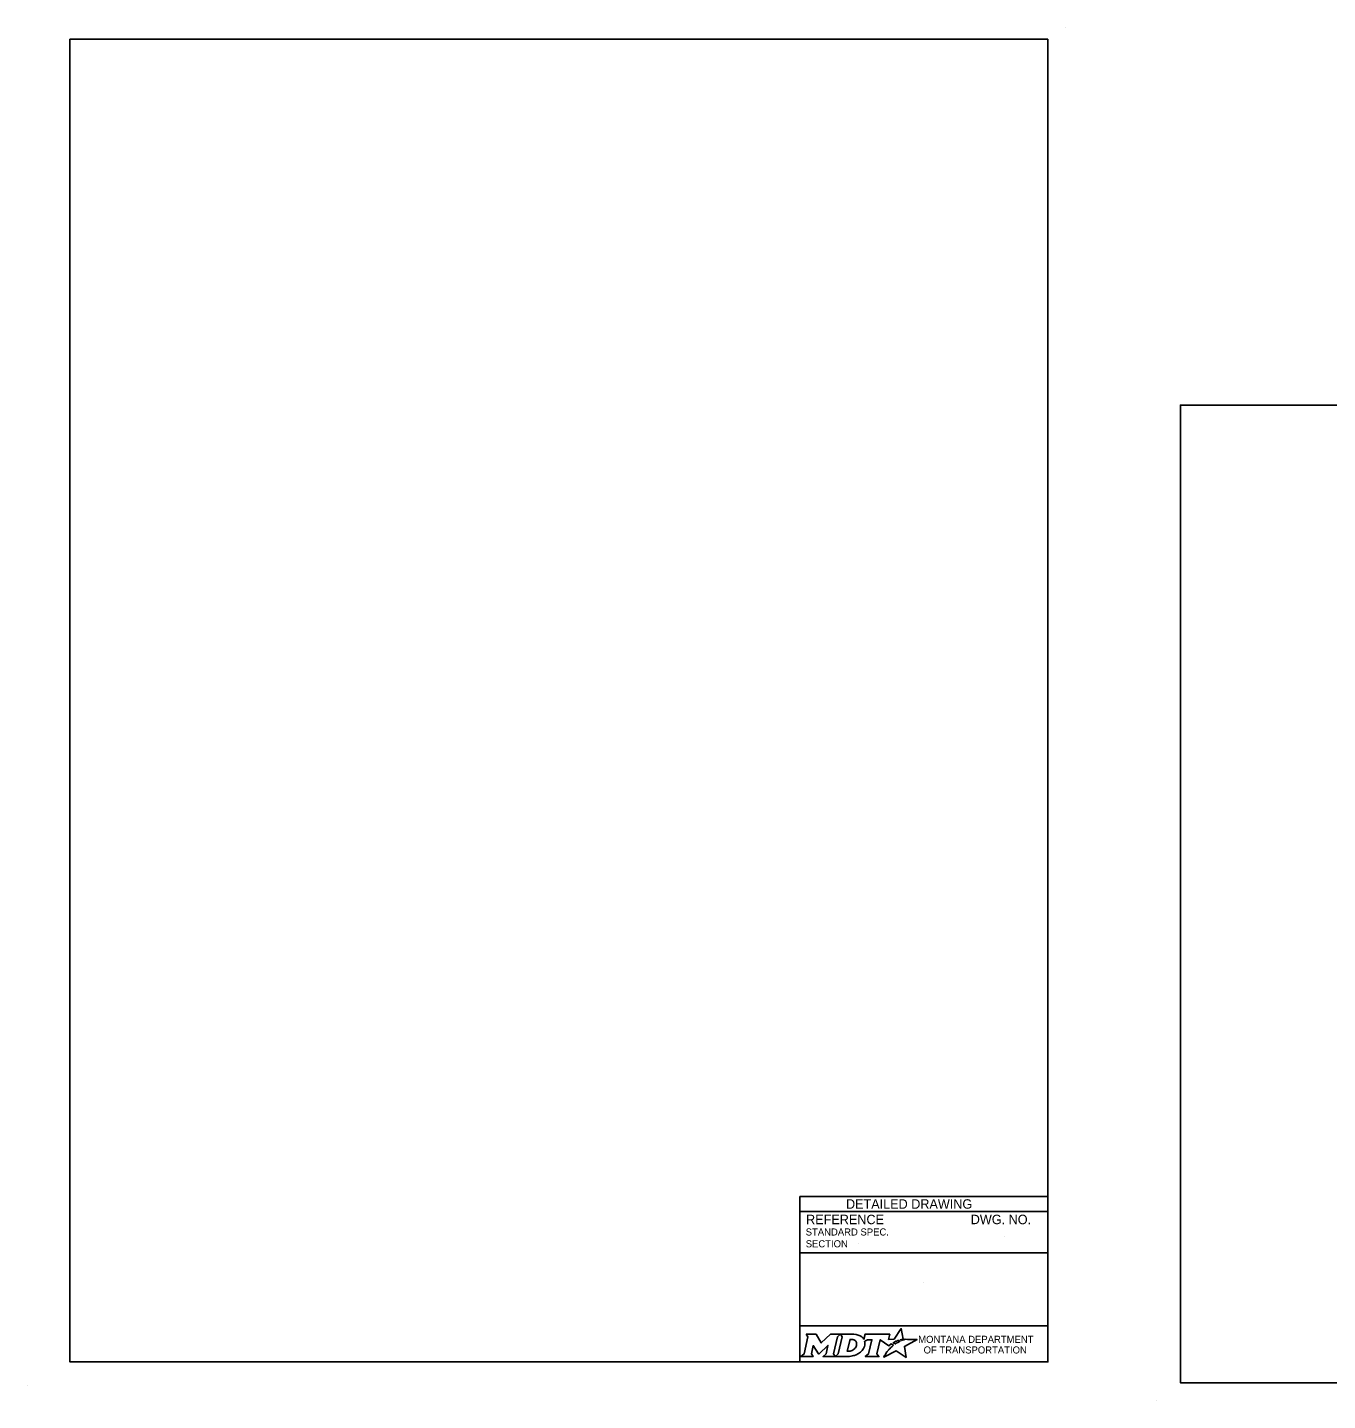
# Model space of a CAD drawing. Extents: x 49991.4 to 50021, y 49987.6 to 50011.4.
# Drawn here: x 49999.98 to 50010.98, y 49999.74 to 50011.36 of the extents above; entities that cross this region are included whole.
import ezdxf

# ---------------------------------------------------------------- set-up
doc = ezdxf.new("R2010")
doc.units = 0
doc.layers.add('Level 1', color=7, linetype='Continuous')
doc.layers.add('Level 2', color=7, linetype='Continuous')

msp = doc.modelspace()

# ---------------------------------------------------------------- linework, layer by layer
at = {"layer": 'Level 1'}
for p, q in [((50008.765, 50011.363), (50008.765, 50011.363)), ((49999.977, 49999.862), (49999.977, 49999.862)), ((50009.537, 49999.736), (50009.537, 49999.736))]:
    msp.add_line(p, q, dxfattribs=at)
for points in [[(50008.615, 50011.263), (50000.336, 50011.263), (50000.336, 50000.062), (50008.615, 50000.062)], [(50020.938, 50008.165), (50009.737, 50008.165), (50009.737, 49999.886), (50020.938, 49999.886)]]:
    msp.add_lwpolyline(points, close=True, dxfattribs=at)
at = {"layer": 'Level 2'}
for p, q in [((50008.615, 50001.462), (50006.515, 50001.462)), ((50006.515, 50001.462), (50006.515, 50000.062)), ((50008.615, 50001.337), (50006.515, 50001.337)), ((50007.009, 50001.063), (50007.009, 50001.063)), ((50008.251, 50001.122), (50008.251, 50001.122)), ((50008.615, 50000.987), (50006.515, 50000.987)), ((50007.565, 50000.738), (50007.565, 50000.738)), ((50008.615, 50000.369), (50006.515, 50000.369))]:
    msp.add_line(p, q, dxfattribs=at)
for points in [[(50007.377, 50000.245), (50007.367, 50000.25), (50007.378, 50000.253), (50007.39, 50000.255), (50007.373, 50000.345), (50007.313, 50000.254), (50007.266, 50000.253), (50007.276, 50000.297), (50007.067, 50000.297), (50007.057, 50000.255), (50007.051, 50000.263)], [(50006.57, 50000.297), (50006.584, 50000.274), (50006.551, 50000.131), (50006.525, 50000.108), (50006.627, 50000.108), (50006.613, 50000.131), (50006.629, 50000.201), (50006.673, 50000.132), (50006.678, 50000.132), (50006.753, 50000.202), (50006.737, 50000.13), (50006.712, 50000.108), (50006.814, 50000.108), (50006.8, 50000.132), (50006.833, 50000.274)], [(50006.833, 50000.274), (50006.859, 50000.297), (50006.776, 50000.297), (50006.697, 50000.224), (50006.652, 50000.297), (50006.57, 50000.297)], [(50006.972, 50000.297), (50006.859, 50000.297), (50006.873, 50000.275), (50006.839, 50000.131), (50006.814, 50000.108), (50006.925, 50000.108)], [(50006.996, 50000.211), (50006.995, 50000.203), (50006.992, 50000.193), (50006.988, 50000.185), (50006.982, 50000.178), (50006.976, 50000.171), (50006.968, 50000.164), (50006.959, 50000.16), (50006.95, 50000.156), (50006.941, 50000.154), (50006.932, 50000.153), (50006.916, 50000.153), (50006.94, 50000.253), (50006.956, 50000.253), (50006.963, 50000.252), (50006.971, 50000.25), (50006.977, 50000.247), (50006.983, 50000.243), (50006.988, 50000.238), (50006.992, 50000.232), (50006.995, 50000.226), (50006.996, 50000.218), (50006.996, 50000.215), (50006.996, 50000.211)], [(50007.064, 50000.238), (50007.088, 50000.251), (50007.125, 50000.251), (50007.097, 50000.131), (50007.069, 50000.108), (50007.185, 50000.108), (50007.168, 50000.131), (50007.196, 50000.251), (50007.268, 50000.2), (50007.289, 50000.215), (50007.309, 50000.204)], [(50007.253, 50000.148), (50007.237, 50000.124), (50007.233, 50000.116), (50007.227, 50000.107), (50007.225, 50000.103), (50007.33, 50000.156), (50007.414, 50000.101), (50007.401, 50000.194), (50007.508, 50000.252), (50007.458, 50000.253), (50007.428, 50000.253), (50007.407, 50000.254), (50007.401, 50000.252), (50007.396, 50000.251), (50007.387, 50000.249), (50007.377, 50000.245)], [(50007.327, 50000.217), (50007.324, 50000.215), (50007.306, 50000.225), (50007.316, 50000.231), (50007.32, 50000.233), (50007.329, 50000.237), (50007.335, 50000.239), (50007.343, 50000.243), (50007.35, 50000.245), (50007.362, 50000.238), (50007.358, 50000.236), (50007.353, 50000.233), (50007.349, 50000.231), (50007.344, 50000.228), (50007.342, 50000.227), (50007.339, 50000.225), (50007.337, 50000.224), (50007.334, 50000.222), (50007.332, 50000.221), (50007.329, 50000.219), (50007.327, 50000.217)], [(50006.97, 50000.116), (50006.979, 50000.118), (50006.992, 50000.124), (50007.012, 50000.135)], [(50007.267, 50000.164), (50007.267, 50000.164)]]:
    msp.add_lwpolyline(points, dxfattribs=at)
for centre, radius, start, end in [((50006.995, 50000.219), 0.0709, 339.5329, 15.8582), ((50006.951, 50000.236), 0.118, 300.9103, 339.1383)]:
    msp.add_arc(centre, radius, start, end, dxfattribs=at)
for centre, major_axis, ratio, start_param, end_param in [((50006.97, 50000.25), (0.0834, -0.0037), 0.568097, 0.61298, 1.570796), ((50007.026, 50000.257), (0.0361, -0.0295), 0.469099, 1.225588, 1.570796), ((50006.925, 50000.257), (0, 0.148), 0.987302, 3.139398, 3.456847), ((50007.26, 50000.156), (-0.00694, -0.00806), 0.008222, 0, 3.137361), ((50007.276, 50000.174), (-0.0098, -0.0102), 0.016458, 3.141593, 6.279097), ((50007.297, 50000.194), (-0.0112, -0.0097), 0.021651, 3.157348, 6.283185)]:
    msp.add_ellipse(centre, major_axis=major_axis, ratio=ratio, start_param=start_param, end_param=end_param, dxfattribs=at)

# ---------------------------------------------------------------- texts
for s, height, p in [('DETAILED DRAWING', 0.0799, (50006.906, 50001.36)), ('REFERENCE', 0.08, (50006.568, 50001.229)), ('DWG. NO.', 0.08, (50007.962, 50001.229)), ('STANDARD SPEC.', 0.06, (50006.565, 50001.133)), ('SECTION', 0.06, (50006.565, 50001.033))]:
    msp.add_text(s, height=height, dxfattribs=at).set_placement(p)
for s, p in [('MONTANA DEPARTMENT', (50007.517, 50000.224)), ('OF TRANSPORTATION', (50007.563, 50000.134))]:
    msp.add_text(s, height=0.06, rotation=360, dxfattribs=at).set_placement(p)

doc.saveas('drawing.dxf')
